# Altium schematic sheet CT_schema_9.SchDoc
size 287 x 160 mm
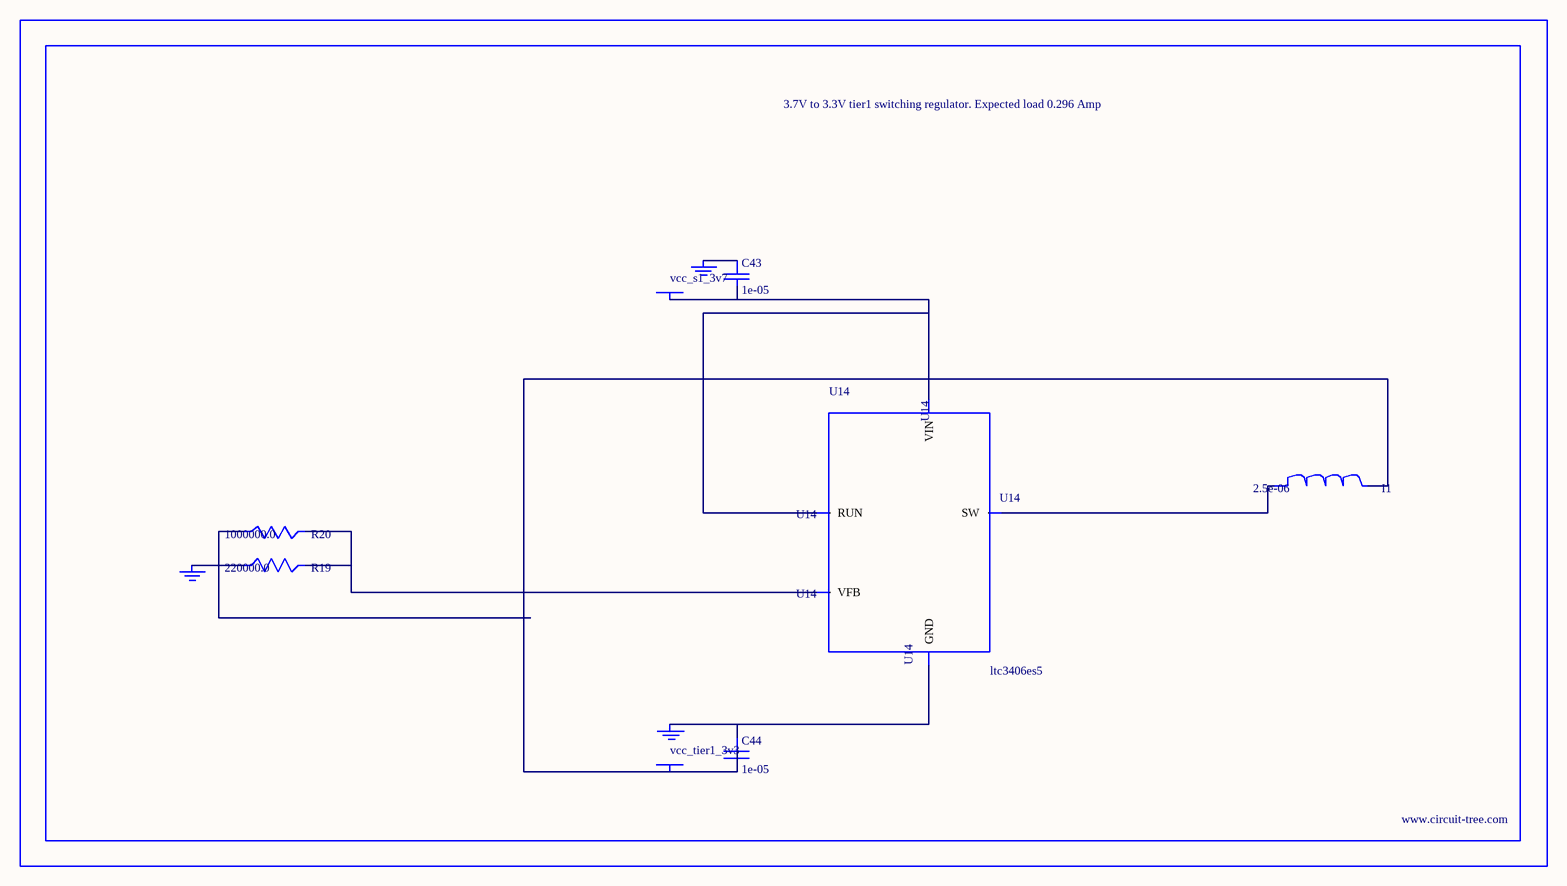
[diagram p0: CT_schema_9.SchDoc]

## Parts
BORDER8  (no value)
C43  1e-05  [C0805]
C44  1e-05  [C0805]
GND_INSTANCE_8_0  (no value)
GND_INSTANCE_8_1  (no value)
GND_INSTANCE_8_2  (no value)
I1  2.5e-06  [DR1040]
POWER_INSTANCE_8_0  vcc_tier1_3v3
POWER_INSTANCE_8_1  vcc_s1_3v7
R19  220000.0  [R0603]
R20  1000000.0  [R0603]
U14  ltc3406es5  [TSOT-23-5]

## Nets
NetC43_1: C43.1 GND_INSTANCE_8_1.0(GND)
NetC43_2: C43.2 POWER_INSTANCE_8_1.0(PWR) U14.1(RUN) U14.4(VIN)
NetC44_1: C44.1 GND_INSTANCE_8_0.0(GND) U14.2(GND)
NetC44_2: C44.2 I1.2 POWER_INSTANCE_8_0.0(PWR) R20.1
NetGND_INSTANCE_8_2_0: GND_INSTANCE_8_2.0(GND) R19.1
NetI1_1: I1.1 U14.3(SW)
NetR19_2: R19.2 R20.2 U14.5(VFB)

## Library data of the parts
BORDER8 = BORDER_PAGE8
C43 C44 = C0805C106K8RACTU
GND_INSTANCE_8_0-GND_INSTANCE_8_2 = GND
I1 = DR1040-2R5-R
POWER_INSTANCE_8_0 POWER_INSTANCE_8_1 = PWR
R19 = RC0603JR-07220KL
R20 = RC0603JR-071ML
